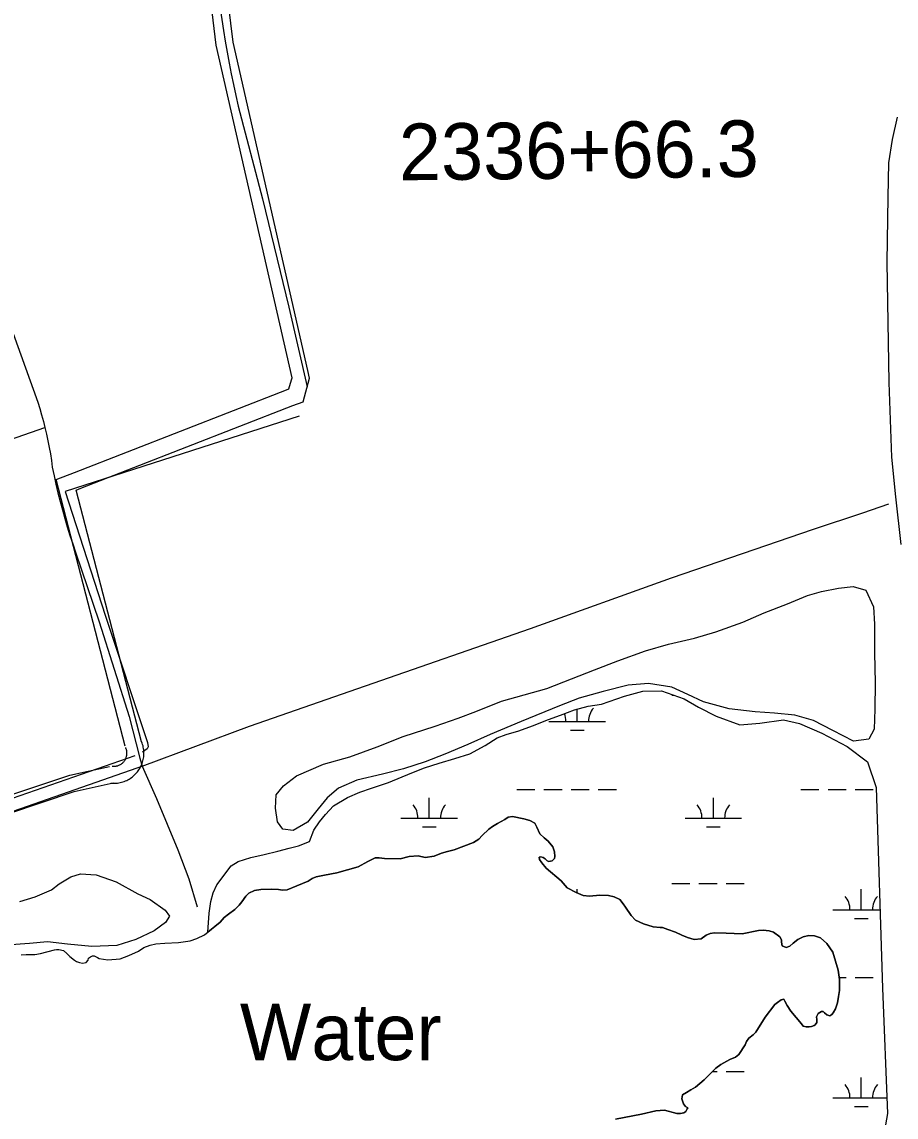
# Model space of a CAD drawing. Extents: x 3535183 to 3573198, y 534952 to 560562.
# Drawn here: x 3544813 to 3546358, y 554225 to 556160 of the extents above; entities that cross this region are included whole.
import ezdxf

# ---------------------------------------------------------------- set-up
doc = ezdxf.new("R2010")
doc.units = 0
for name, color, linetype in [('V-DTCH-CNTR', 7, 'Continuous'), ('V-RIVR-IDEN', 7, 'Continuous'), ('V-ROAD-CNTR', 7, 'Continuous'), ('V-SITE-VEGE', 7, 'Continuous'), ('V-SURV-IDEN', 7, 'Continuous'), ('V-TOPO-SHOR', 7, 'Continuous'), ('V-WETL-SWMP', 7, 'Continuous')]:
    doc.layers.add(name, color=color, linetype=linetype)

msp = doc.modelspace()

# ---------------------------------------------------------------- linework, layer by layer
at = {"layer": 'V-DTCH-CNTR'}
for points in [[(3545117.1, 556939.1), (3545120.1, 556906.1), (3545122.8, 556873.2), (3545125.5, 556840.2), (3545128, 556807.2), (3545133.5, 556713.4), (3545138.8, 556570.1), (3545146.9, 556402.2), (3545156.4, 556242.1), (3545158.6, 556222.7), (3545160.9, 556203.3), (3545163.5, 556184), (3545166.2, 556164.7), (3545169.2, 556145.4), (3545172.3, 556126.2), (3545175.7, 556107), (3545179.2, 556087.8), (3545183, 556068.7), (3545186.9, 556049.6), (3545191, 556030.5), (3545195.4, 556011.5), (3545238.1, 555847.9), (3545284.6, 555656.1), (3545317.2, 555515.6)], [(3544797.6, 555609.8), (3544841, 555488.1), (3544844.6, 555477), (3544847.9, 555465.7), (3544851, 555454.4), (3544853.8, 555443.5), (3544856.6, 555431.6), (3544859.1, 555420.1), (3544861.3, 555408.5), (3544863.3, 555397), (3544865.1, 555385.3), (3544866.6, 555373.7), (3544869.8, 555358.4), (3544873.1, 555343.2), (3544876.7, 555328), (3544880.5, 555312.9), (3544884.5, 555297.8), (3544888.8, 555282.8), (3544893.2, 555267.9), (3544897.9, 555253), (3544902.8, 555238.2), (3544907.8, 555223.4), (3544949.8, 555100), (3545002.5, 554932.9)], [(3544048.9, 555159.4), (3544147.7, 555192.2), (3544315.1, 555250.8), (3544487.6, 555314.4), (3544654.6, 555376.7), (3544804.8, 555426.6), (3544853.8, 555443.5)], [(3543210.8, 554212), (3543385.2, 554270.5), (3543578.6, 554337.5), (3543771.9, 554404.8), (3543990.6, 554481.4), (3544167.2, 554544.2), (3544240.5, 554570.4), (3544356.7, 554609.7), (3544543.2, 554678.4), (3544786, 554761.5), (3545016.6, 554841.8), (3545025.7, 554845.2), (3545215.3, 554916), (3545420, 554987.1), (3545711.4, 555088.1), (3545961, 555177.6), (3546211.5, 555263.9), (3546298.6, 555292.6), (3546344.9, 555308.7)], [(3545002.5, 554932.9), (3545021.1, 554858.9), (3545025.7, 554845.2), (3545051, 554788), (3545088.3, 554697.3), (3545108.1, 554646), (3545122.9, 554596.5)]]:
    msp.add_lwpolyline(points, dxfattribs=at)
at = {"layer": 'V-ROAD-CNTR'}
for points in [[(3545318.2, 555544.6), (3545186.1, 556124.4), (3545173.4, 556230.9), (3545160.1, 556375), (3545131.8, 556850.4), (3545122.8, 556929.4)], [(3545289.4, 555527.8), (3545290.4, 555531.5), (3545156.5, 556119.3), (3545143.5, 556227.7), (3545130.2, 556372.7), (3545101.9, 556847.8), (3545093.6, 556920.4)], [(3546359.5, 555991.9), (3546350.5, 555952.7), (3546344.1, 555911.5), (3546343, 555850.7), (3546341.5, 555735.6), (3546344.8, 555523.3), (3546349.2, 555391.4), (3546356.8, 555321.3), (3546365.7, 555236.8)], [(3545291.9, 555482.2), (3545309.7, 555489.1), (3545321.3, 555530.7), (3545318.2, 555544.6)], [(3545280.3, 555509.9), (3545284.9, 555511.7), (3545289.4, 555527.8)], [(3544905.8, 555364), (3545280.3, 555509.9)], [(3544917.4, 555336.3), (3545291.9, 555482.2)], [(3544995.4, 554880.5), (3544873.4, 555351.4), (3544905.8, 555364)], [(3545024.4, 554888), (3544909.1, 555333.1), (3544917.4, 555336.3)], [(3544970, 554815.1), (3544972.1, 554815), (3544974.5, 554814.9), (3544976.9, 554814.9), (3544979.3, 554815), (3544981.8, 554815.2), (3544984.2, 554815.6), (3544986.6, 554816), (3544988.9, 554816.6), (3544991.3, 554817.3), (3544993.6, 554818), (3544995.8, 554818.9), (3544998.1, 554819.9), (3545000.2, 554821), (3545002.4, 554822.2), (3545004.4, 554823.4), (3545006.4, 554824.8), (3545008.4, 554826.3), (3545010.3, 554827.8), (3545012.1, 554829.5), (3545013.8, 554831.2), (3545015.4, 554833), (3545017, 554834.9), (3545018.5, 554836.8), (3545019.8, 554838.8), (3545021.1, 554840.9), (3545022.3, 554843), (3545023.4, 554845.2), (3545024.4, 554847.4), (3545025.3, 554849.6), (3545026.1, 554851.9), (3545026.8, 554854.3), (3545027.3, 554856.6), (3545027.8, 554859), (3545028.2, 554861.4), (3545028.4, 554863.9), (3545028.5, 554866.3), (3545028.6, 554868.7), (3545028.5, 554871.1), (3545028.3, 554873.6), (3545027.9, 554876), (3545027.5, 554878.4), (3545027, 554880.8), (3545026.3, 554883.1), (3545025.6, 554885.4), (3545024.7, 554887.7), (3545023.8, 554889.8), (3545023.5, 554890.6)], [(3544972.6, 554845), (3544974, 554844.9), (3544975, 554844.9), (3544976.1, 554844.9), (3544977.2, 554844.9), (3544978.2, 554845), (3544979.3, 554845.2), (3544980.3, 554845.4), (3544981.3, 554845.6), (3544982.3, 554845.9), (3544983.3, 554846.2), (3544984.3, 554846.6), (3544985.3, 554847.1), (3544986.2, 554847.5), (3544987.2, 554848), (3544988.1, 554848.6), (3544988.9, 554849.2), (3544989.8, 554849.8), (3544990.6, 554850.5), (3544991.4, 554851.2), (3544992.1, 554852), (3544992.8, 554852.7), (3544993.5, 554853.6), (3544994.2, 554854.4), (3544994.8, 554855.3), (3544995.3, 554856.2), (3544995.8, 554857.1), (3544996.3, 554858), (3544996.7, 554859), (3544997.1, 554860), (3544997.5, 554861), (3544997.8, 554862), (3544998, 554863), (3544998.2, 554864.1), (3544998.4, 554865.1), (3544998.5, 554866.2), (3544998.5, 554867.2), (3544998.5, 554868.3), (3544998.5, 554869.3), (3544998.4, 554870.4), (3544998.3, 554871.4), (3544998.1, 554872.5), (3544997.9, 554873.5), (3544997.6, 554874.5), (3544997.3, 554875.5), (3544996.9, 554876.5), (3544996.4, 554877.6), (3544996.3, 554877.9)], [(3544664.4, 554751.1), (3544897.5, 554829), (3544968, 554844.7)], [(3544673.9, 554722.7), (3544905.6, 554800.1), (3544974.5, 554815.4)]]:
    msp.add_lwpolyline(points, dxfattribs=at)
at = {"layer": 'V-SITE-VEGE'}
msp.add_lwpolyline([(3546303.9, 555156.2), (3546317.8, 555126.7), (3546319.3, 555095.8), (3546319.6, 555045.2), (3546320.5, 554992.6), (3546320.1, 554946), (3546318.9, 554910.5), (3546309.2, 554892.7), (3546282.2, 554889.3), (3546246, 554908.1), (3546211.7, 554925.7), (3546178.8, 554935.4), (3546142.7, 554938.5), (3546108.5, 554940.9), (3546062.5, 554946.6), (3546017.1, 554958.9), (3545989.4, 554971.9), (3545961.1, 554984.9), (3545920.3, 554991.2), (3545884.2, 554988.4), (3545840.2, 554977), (3545797.6, 554965), (3545762.8, 554951.6), (3545695.3, 554923.7), (3545640.2, 554901.1), (3545600.9, 554883.1), (3545560.2, 554866.5), (3545525.5, 554852.5), (3545487.4, 554840.5), (3545450, 554831.1), (3545404.7, 554820.3), (3545372.6, 554806.4), (3545352.3, 554789.2), (3545336.7, 554769.4), (3545317.7, 554746.3), (3545292.2, 554731.1), (3545273.8, 554733.6), (3545264.5, 554746.7), (3545261.1, 554771), (3545262.3, 554794.6), (3545275.3, 554810.5), (3545298.3, 554827.7), (3545346.1, 554848.3), (3545392.7, 554861.7), (3545440.6, 554879), (3545486.5, 554897.6), (3545542.9, 554915.7), (3545583.6, 554929.7), (3545615, 554941.7), (3545660.3, 554959.7), (3545740.3, 554982.4), (3545784.3, 554999.1), (3545824.9, 555015), (3545866.2, 555031), (3545914.8, 555049), (3545955.4, 555060.4), (3546001.4, 555071.1), (3546039.4, 555082.5), (3546086.7, 555099.8), (3546124.7, 555115.8), (3546166, 555131.8), (3546200.8, 555146.4), (3546225.7, 555153.8), (3546255.9, 555159.8), (3546281.5, 555162.6)], close=True, dxfattribs=at)
msp.add_lwpolyline([(3544809.5, 554606.1), (3544836.4, 554614.1), (3544865.3, 554626.7), (3544879, 554637.3), (3544899.3, 554649.3), (3544916.4, 554654.6), (3544944, 554652.8), (3544979.6, 554640.5), (3545017.8, 554619.6), (3545039.5, 554609.2), (3545065.9, 554590.3), (3545073.8, 554579.8), (3545066.7, 554568.6), (3545046.4, 554554.1), (3545014.2, 554538.8), (3544980.8, 554528.1), (3544936.8, 554526.6), (3544893.4, 554530.3), (3544858.5, 554534.7), (3544826.4, 554531.9), (3544785.6, 554528.4)], dxfattribs=at)
at = {"layer": 'V-TOPO-SHOR'}
for points in [[(3545303.1, 555463.5), (3544889.2, 555330.7), (3544959.9, 555112.2), (3545034.8, 554886.8), (3545035.8, 554879.1), (3545034.4, 554875.9), (3545026, 554869.5)], [(3545012.4, 554863), (3544741, 554769.3), (3544415.7, 554652.5), (3544249, 554593.3)], [(3544811.7, 554511.8), (3544820.8, 554512.3), (3544835.8, 554511.9), (3544845.8, 554513.8), (3544870.8, 554520.3), (3544874.4, 554520.8), (3544878.1, 554520.8), (3544886.3, 554519), (3544892.6, 554514), (3544897.7, 554508.6), (3544905.9, 554502.3), (3544909.6, 554500), (3544914.6, 554497.8), (3544920, 554496.9), (3544926.4, 554498.3), (3544930, 554501.9), (3544930.9, 554505.6), (3544934.1, 554508.3), (3544937.7, 554509.7), (3544940.9, 554509.7), (3544946.8, 554506.6), (3544949.6, 554505.2), (3544965.1, 554502.6), (3544986.9, 554504.5), (3545001.9, 554510.5), (3545019.1, 554518.3), (3545028.2, 554524.3), (3545039.6, 554528.9), (3545049.6, 554531.2), (3545065.5, 554532.2), (3545089.6, 554533.3), (3545110.5, 554536.1), (3545121.9, 554540.7), (3545135.5, 554547.1), (3545163.6, 554569.6), (3545170.4, 554577.8), (3545178.1, 554583.3), (3545189.4, 554591.6), (3545196.7, 554599.3), (3545201.6, 554605.3), (3545208.9, 554615.3), (3545213.8, 554620.8), (3545223.8, 554625), (3545235.2, 554627.3), (3545254.8, 554627.9), (3545266.1, 554627), (3545273.4, 554625.7), (3545281.6, 554626.6), (3545298.9, 554633.5), (3545318.9, 554641.8), (3545326.1, 554646.4), (3545332.9, 554649.2), (3545347.5, 554652.5), (3545369.3, 554656.7), (3545407, 554667.3), (3545424.3, 554676.5), (3545437, 554683), (3545444.2, 554683), (3545453.8, 554681.7), (3545481.6, 554681.4), (3545497, 554685.1), (3545512.9, 554686.5), (3545525.7, 554683.9), (3545541.6, 554685.8), (3545554.3, 554691.3), (3545565.2, 554694.5), (3545576.6, 554696.9), (3545610.7, 554710.2), (3545620.6, 554716.2), (3545626.5, 554722.6), (3545638.3, 554733.6), (3545644.7, 554738.6), (3545653.3, 554743.7), (3545666.4, 554751), (3545672.3, 554754.7), (3545679.6, 554756.1), (3545700.1, 554752.1), (3545710.6, 554749), (3545719.3, 554744), (3545722.9, 554737.2), (3545728, 554725.4), (3545735.8, 554718.6), (3545743.1, 554712.3), (3545751.3, 554702.3), (3545754.1, 554693.7), (3545754.6, 554685.5), (3545754.2, 554681.9)], [(3545730, 554684.9), (3545726.9, 554684), (3545727.8, 554679.9), (3545731.5, 554674), (3545739.2, 554664.9), (3545765.7, 554642.3), (3545776.3, 554630.1), (3545792.2, 554621.5), (3545804.6, 554616.6), (3545815.9, 554615.3), (3545834.1, 554617.2), (3545849.2, 554616.4), (3545859.6, 554614.1), (3545869.2, 554609.6), (3545875.2, 554601.5), (3545879.3, 554595.6), (3545889.8, 554581.1), (3545897.2, 554572.9), (3545911.3, 554566.2), (3545928.2, 554561.2), (3545940.9, 554559.9), (3545945, 554560), (3545954.1, 554556.4), (3545967.8, 554551.4), (3545979.2, 554546.5), (3545989.3, 554542), (3546000.6, 554538.9), (3546012.9, 554539.8), (3546022, 554546.3), (3546029.3, 554549.5), (3546036.5, 554550.4), (3546057.5, 554549.6), (3546085.7, 554548.9), (3546114.3, 554554.5), (3546122.5, 554555), (3546133.5, 554554.1), (3546141.2, 554551.4), (3546152.2, 554543.3), (3546154.9, 554538.3), (3546154.9, 554534.2), (3546156.3, 554527.4), (3546163.2, 554524.7), (3546170, 554527), (3546175.9, 554532), (3546184.1, 554538.5), (3546193.6, 554543.1), (3546203.6, 554545.8), (3546213.6, 554545.4), (3546224.1, 554541.4), (3546235.5, 554531.9), (3546245.6, 554516), (3546255.3, 554484.2), (3546257.7, 554467.8), (3546257.8, 554448.7), (3546256, 554437.8), (3546253.8, 554426.9), (3546250.7, 554415.9), (3546246.6, 554409.1), (3546243.9, 554405.9), (3546240.7, 554403.6), (3546235.2, 554405.8), (3546231.1, 554409), (3546228.8, 554411.7), (3546225.7, 554411.2), (3546220.2, 554408), (3546217.1, 554402.1), (3546217.5, 554397.1), (3546217.6, 554392.1), (3546214.4, 554388), (3546212.6, 554386.6), (3546208.1, 554385.2), (3546204, 554384.3), (3546199, 554384.3), (3546193.5, 554385.6), (3546190.3, 554389.7), (3546171.5, 554411.9), (3546165.1, 554422.3), (3546160.9, 554429.6), (3546159.1, 554433.2), (3546154.6, 554432.3), (3546147.8, 554427.2), (3546143.2, 554424), (3546126.5, 554401.2), (3546109.8, 554374.7), (3546105.3, 554370.1), (3546097.6, 554364.2), (3546093.5, 554358.2), (3546090.8, 554352.8), (3546080, 554335.4), (3546073.6, 554330.8), (3546063.6, 554326.7), (3546047.8, 554317.5), (3546039.1, 554311.1), (3546018.3, 554290.9), (3546002.9, 554277.7)], [(3545754.2, 554681.9), (3545750.1, 554677.7), (3545744.2, 554676.8), (3545741, 554677.7), (3545737.8, 554681.3), (3545734.1, 554683.6), (3545730, 554684.9)], [(3546002.9, 554277.7), (3545995.2, 554273.1), (3545987.5, 554268.5), (3545980.2, 554263.9), (3545978.9, 554257.1), (3545981.7, 554248), (3545985.3, 554243.4)], [(3545985.3, 554243.4), (3545989.4, 554241.2), (3545988.5, 554239.4), (3545986.3, 554234.8), (3545982.7, 554232.1), (3545976.8, 554231.1), (3545970.4, 554231.1), (3545948.5, 554237.3), (3545933, 554235.9), (3545907.6, 554229.8), (3545861.7, 554221)]]:
    msp.add_lwpolyline(points, dxfattribs=at)
at = {"layer": 'V-WETL-SWMP'}
for p, q in [((3545961.3, 554970.5), (3545964.8, 554970.5)), ((3545794.2, 554924.1), (3545794.2, 554945.8)), ((3545744.2, 554924.1), (3545844.2, 554924.1)), ((3545782.2, 554908.7), (3545806.2, 554908.7)), ((3545687.3, 554804), (3545719.3, 554804)), ((3545735.3, 554804), (3545767.3, 554804)), ((3545783.3, 554804), (3545815.3, 554804)), ((3545831.3, 554804), (3545863.3, 554804)), ((3546189.3, 554804), (3546221.3, 554804)), ((3546237.3, 554804), (3546269.3, 554804)), ((3546285.3, 554804), (3546317.3, 554804)), ((3545532.8, 554753.3), (3545532.8, 554789.3)), ((3546034.7, 554753.3), (3546034.7, 554789.3)), ((3545482.8, 554753.3), (3545582.8, 554753.3)), ((3545984.7, 554753.3), (3546084.7, 554753.3)), ((3545520.8, 554737.9), (3545544.8, 554737.9)), ((3546022.7, 554737.9), (3546046.7, 554737.9)), ((3545794.2, 554620.8), (3545794.2, 554627.4)), ((3545961.3, 554637.9), (3545993.3, 554637.9)), ((3546009.3, 554637.9), (3546041.3, 554637.9)), ((3546057.3, 554637.9), (3546089.3, 554637.9)), ((3546296.1, 554591.4), (3546296.1, 554627.4)), ((3546246.1, 554591.4), (3546329.1, 554591.4)), ((3546284.1, 554576), (3546308.1, 554576)), ((3546257.2, 554471.4), (3546269.3, 554471.4)), ((3546285.3, 554471.4), (3546317.3, 554471.4)), ((3546033.1, 554305.2), (3546041.3, 554305.2)), ((3546057.3, 554305.2), (3546089.3, 554305.2)), ((3546296.1, 554258.8), (3546296.1, 554294.8)), ((3546246.1, 554258.8), (3546341.6, 554258.8)), ((3546284.1, 554243.3), (3546308.1, 554243.3))]:
    msp.add_line(p, q, dxfattribs=at)
for points in [[(3545730, 554684.9), (3545734.1, 554683.6), (3545737.8, 554681.3), (3545741, 554677.7), (3545744.2, 554676.8), (3545750.1, 554677.7), (3545754.2, 554681.9), (3545754.6, 554685.5), (3545754.1, 554693.7), (3545751.3, 554702.3), (3545743.1, 554712.3), (3545735.8, 554718.6), (3545728, 554725.4), (3545722.9, 554737.2), (3545719.3, 554744), (3545710.6, 554749), (3545700.1, 554752.1), (3545679.6, 554756.1), (3545672.3, 554754.7), (3545666.4, 554751), (3545653.3, 554743.7), (3545644.7, 554738.6), (3545638.3, 554733.6), (3545626.5, 554722.6), (3545620.6, 554716.2), (3545610.7, 554710.2), (3545576.6, 554696.9), (3545565.2, 554694.5), (3545554.3, 554691.3), (3545541.6, 554685.8), (3545525.7, 554683.9), (3545512.9, 554686.5), (3545497, 554685.1), (3545481.6, 554681.4), (3545453.8, 554681.7), (3545444.2, 554683), (3545437, 554683), (3545424.3, 554676.5), (3545407, 554667.3), (3545369.3, 554656.7), (3545347.5, 554652.5), (3545332.9, 554649.2), (3545326.1, 554646.4), (3545318.9, 554641.8), (3545298.9, 554633.5), (3545281.6, 554626.6), (3545273.4, 554625.7), (3545266.1, 554627), (3545254.8, 554627.9), (3545235.2, 554627.3), (3545223.8, 554625), (3545213.8, 554620.8), (3545208.9, 554615.3), (3545201.6, 554605.3), (3545196.7, 554599.3), (3545189.4, 554591.6), (3545178.1, 554583.3), (3545170.4, 554577.8), (3545163.6, 554569.6), (3545141.5, 554551.9), (3545143.6, 554585.2), (3545146.6, 554605.6), (3545151.1, 554621.1), (3545157.4, 554635.3), (3545182.7, 554669.1), (3545195, 554676.4), (3545217.7, 554683.4), (3545241.3, 554689), (3545265.4, 554695), (3545285, 554700.1), (3545301.8, 554704.3), (3545321.3, 554712.1), (3545328.9, 554731.7), (3545338.9, 554746.4), (3545349.7, 554759.6), (3545363.8, 554774.7), (3545388.3, 554789.8), (3545410.1, 554799.1), (3545430.5, 554806), (3545460.5, 554816.2), (3545501.8, 554833.2), (3545524.1, 554842), (3545550, 554850.3), (3545578.1, 554858.6), (3545604.5, 554867), (3545631.3, 554881.7), (3545653, 554895), (3545668.9, 554901), (3545691.2, 554907.4), (3545715.3, 554916.2), (3545743.4, 554927.3), (3545764.8, 554935.1), (3545789.3, 554944.4), (3545813.4, 554951.3), (3545837, 554954.6), (3545877.9, 554968.9), (3545910.2, 554977.8), (3545943, 554978.4), (3545983.1, 554964), (3546008.6, 554949.6), (3546039.7, 554933.4)], [(3546039.7, 554933.4), (3546081.6, 554918.1), (3546117.1, 554921), (3546158.9, 554926.7), (3546187.2, 554920.5), (3546226.4, 554903.4), (3546271.1, 554880), (3546306.8, 554852.8), (3546322.5, 554807.4), (3546333.4, 554452.5), (3546342.7, 554231.4), (3546337.4, 554201.3)], [(3545985.3, 554243.4), (3545981.7, 554248), (3545978.9, 554257.1), (3545980.2, 554263.9), (3545987.5, 554268.5), (3545995.2, 554273.1), (3546002.9, 554277.7), (3546018.3, 554290.9), (3546039.1, 554311.1), (3546047.8, 554317.5), (3546063.6, 554326.7), (3546073.6, 554330.8), (3546080, 554335.4), (3546090.8, 554352.8), (3546093.5, 554358.2), (3546097.6, 554364.2), (3546105.3, 554370.1), (3546109.8, 554374.7), (3546126.5, 554401.2), (3546143.2, 554424), (3546147.8, 554427.2), (3546154.6, 554432.3), (3546159.1, 554433.2), (3546160.9, 554429.6), (3546165.1, 554422.3), (3546171.5, 554411.9), (3546190.3, 554389.7), (3546193.5, 554385.6), (3546199, 554384.3), (3546204, 554384.3), (3546208.1, 554385.2), (3546212.6, 554386.6), (3546214.4, 554388), (3546217.6, 554392.1), (3546217.5, 554397.1), (3546217.1, 554402.1), (3546220.2, 554408), (3546225.7, 554411.2), (3546228.8, 554411.7), (3546231.1, 554409), (3546235.2, 554405.8), (3546240.7, 554403.6), (3546243.9, 554405.9), (3546246.6, 554409.1), (3546250.7, 554415.9), (3546253.8, 554426.9), (3546256, 554437.8), (3546257.8, 554448.7), (3546257.7, 554467.8), (3546255.3, 554484.2), (3546245.6, 554516), (3546235.5, 554531.9), (3546224.1, 554541.4), (3546213.6, 554545.4), (3546203.6, 554545.8), (3546193.6, 554543.1), (3546184.1, 554538.5), (3546175.9, 554532), (3546170, 554527), (3546163.2, 554524.7), (3546156.3, 554527.4), (3546154.9, 554534.2), (3546154.9, 554538.3), (3546152.2, 554543.3), (3546141.2, 554551.4), (3546133.5, 554554.1), (3546122.5, 554555), (3546114.3, 554554.5), (3546085.7, 554548.9), (3546057.5, 554549.6), (3546036.5, 554550.4), (3546029.3, 554549.5), (3546022, 554546.3), (3546012.9, 554539.8), (3546000.6, 554538.9), (3545989.3, 554542), (3545979.2, 554546.5), (3545967.8, 554551.4), (3545954.1, 554556.4), (3545945, 554560), (3545940.9, 554559.9), (3545928.2, 554561.2), (3545911.3, 554566.2), (3545897.2, 554572.9), (3545889.8, 554581.1), (3545879.3, 554595.6), (3545875.2, 554601.5), (3545869.2, 554609.6), (3545859.6, 554614.1), (3545849.2, 554616.4), (3545834.1, 554617.2), (3545815.9, 554615.3), (3545804.6, 554616.6), (3545792.2, 554621.5), (3545776.3, 554630.1), (3545765.7, 554642.3), (3545739.2, 554664.9), (3545731.5, 554674), (3545727.8, 554679.9), (3545726.9, 554684), (3545730, 554684.9)], [(3545861.7, 554221), (3545907.6, 554229.8), (3545933, 554235.9), (3545948.5, 554237.3), (3545970.4, 554231.1), (3545976.8, 554231.1), (3545982.7, 554232.1), (3545986.3, 554234.8), (3545988.5, 554239.4), (3545989.4, 554241.2), (3545985.3, 554243.4)]]:
    msp.add_lwpolyline(points, dxfattribs=at)
for centre, start, end in [((3545738.9, 554924.6), 359.2282, 21.8726), ((3545849.4, 554924.6), 139.2282, 180.7718), ((3545477.5, 554753.8), 359.2282, 40.7718), ((3545588, 554753.8), 139.2282, 180.7718), ((3545979.4, 554753.8), 359.2282, 40.7718), ((3546089.9, 554753.8), 139.2282, 180.7718), ((3546240.9, 554591.9), 359.2282, 40.7718), ((3546351.3, 554591.9), 139.2282, 180.7718), ((3546240.9, 554259.2), 359.2282, 40.7718), ((3546351.3, 554259.2), 139.2282, 180.7718)]:
    msp.add_arc(centre, 35.2, start, end, dxfattribs=at)

# ---------------------------------------------------------------- texts
at = {"layer": 'V-RIVR-IDEN'}
msp.add_text('Water', height=100, dxfattribs=at).set_placement((3545198.1, 554325.4))
at = {"layer": 'V-SURV-IDEN'}
msp.add_text('2336+66.3', height=100, rotation=0.5778, dxfattribs=at).set_placement((3545479.6, 555880.4))

doc.saveas('drawing.dxf')
